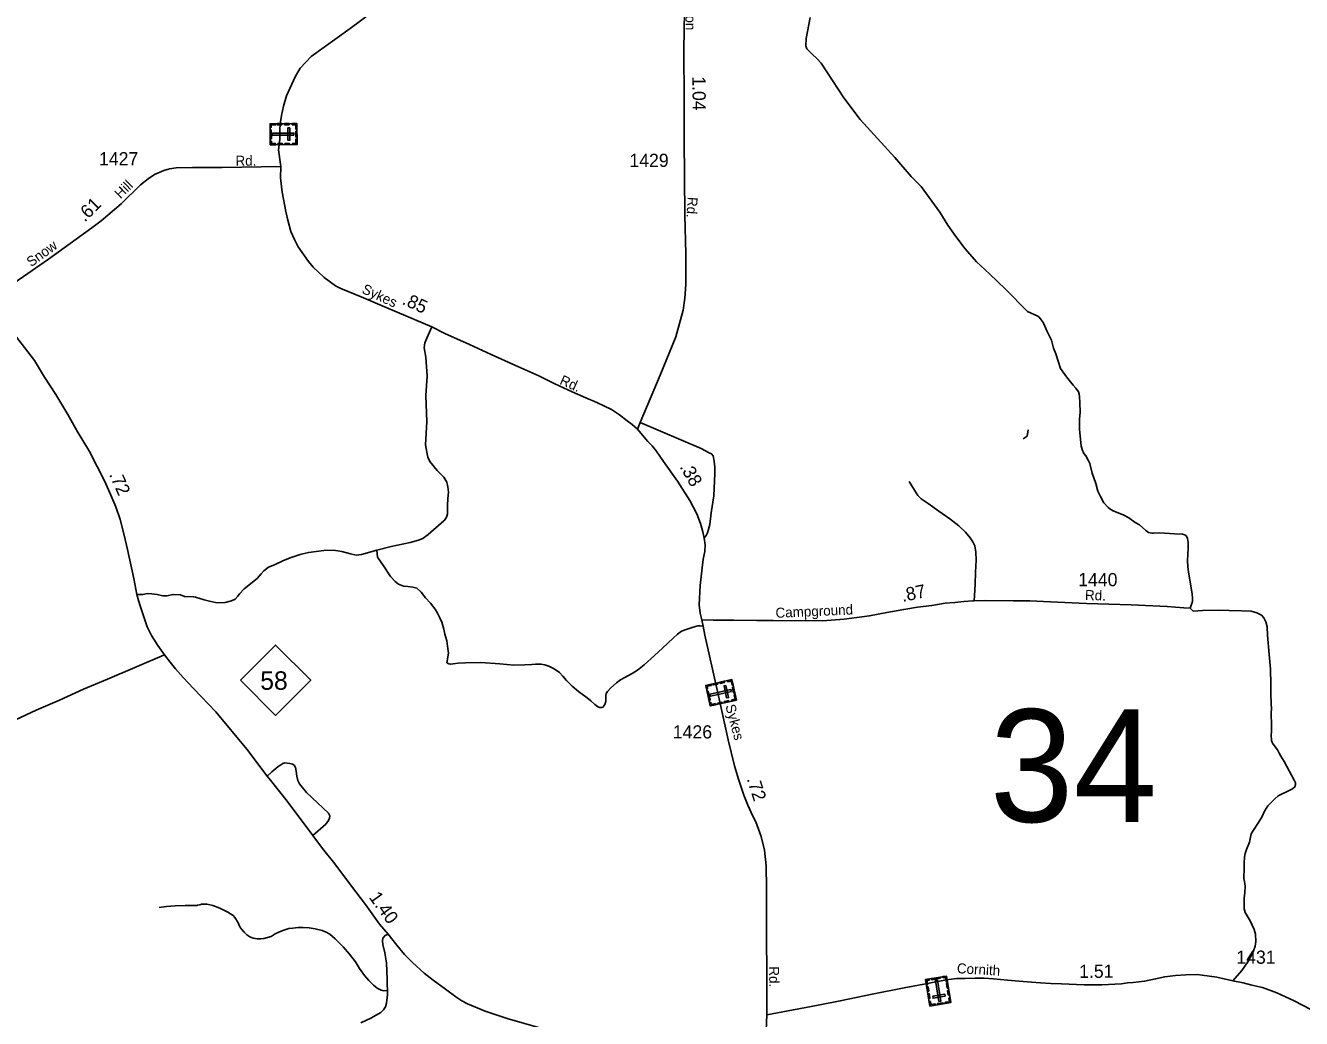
# Model space of a CAD drawing. Extents: x 2220236 to 2384410, y 720751 to 894131.
# Drawn here: x 2286305 to 2298391, y 822579 to 831981 of the extents above; entities that cross this region are included whole.
import ezdxf

# ---------------------------------------------------------------- set-up
doc = ezdxf.new("R2010")
doc.units = 0
doc.layers.add('Default', color=7, linetype='Continuous')

msp = doc.modelspace()

# ---------------------------------------------------------------- linework, layer by layer
at = {"layer": 'Default'}
msp.add_line((2297337, 826463), (2297277, 826468), dxfattribs=at)
for points in [[(2292100, 828159), (2292128, 828223), (2292315, 828671), (2292466, 829034), (2292510, 829194), (2292534, 829287), (2292550, 829398), (2292559, 829530), (2292559, 829818), (2292550, 830184), (2292545, 830909), (2292543, 831273), (2292539, 831754), (2292552, 832468), (2292542, 832714), (2292533, 833135), (2292528, 833487), (2292523, 833575)], [(2289808, 832274), (2289379, 831954), (2289012, 831689), (2288907, 831576), (2288858, 831495), (2288777, 831315), (2288748, 831218), (2288729, 831128), (2288716, 831050), (2288713, 830990), (2288713, 830902), (2288700, 830804), (2288722, 830646)], [(2297337, 826463), (2297358, 826527), (2297358, 826559), (2297355, 826597), (2297321, 826807), (2297314, 826855), (2297312, 826915), (2297319, 827029), (2297316, 827085), (2297311, 827125), (2297305, 827140), (2297297, 827150), (2297285, 827158), (2297265, 827164), (2297189, 827169), (2297047, 827176), (2296993, 827173), (2296973, 827175), (2296943, 827182), (2296915, 827198), (2296856, 827252), (2296816, 827275), (2296754, 827320), (2296707, 827346), (2296607, 827387), (2296575, 827406), (2296559, 827418), (2296518, 827462), (2296486, 827521), (2296463, 827573), (2296442, 827643), (2296409, 827743), (2296386, 827834), (2296370, 827864), (2296349, 827908), (2296329, 827930), (2296315, 827965), (2296304, 828001), (2296287, 828155), (2296288, 828253), (2296293, 828321), (2296292, 828409), (2296289, 828467), (2296285, 828491), (2296279, 828513), (2296255, 828547), (2296228, 828576), (2296165, 828654), (2296109, 828733), (2296065, 828872), (2296043, 828926), (2296022, 829002), (2295979, 829091), (2295950, 829155), (2295944, 829169), (2295924, 829195), (2295910, 829217), (2295893, 829229), (2295795, 829272), (2295587, 829486), (2295436, 829630), (2295313, 829744), (2295206, 829866), (2295118, 829983), (2295040, 830092), (2294966, 830213), (2294789, 830458), (2294695, 830553), (2294538, 830732), (2294211, 831090), (2294055, 831296), (2293841, 831626), (2293802, 831665), (2293753, 831712), (2293705, 831760), (2293695, 831790), (2293700, 831858), (2293736, 832057)], [(2288722, 830646), (2288167, 830637), (2287886, 830637), (2287733, 830634), (2287669, 830623), (2287615, 830609), (2287527, 830569), (2287465, 830530), (2287393, 830472), (2287212, 830293), (2287021, 830132), (2286932, 830066), (2286523, 829770), (2286285, 829604), (2286114, 829487), (2285938, 829362)], [(2288722, 830646), (2288721, 830538), (2288736, 830403), (2288770, 830221), (2288788, 830137), (2288819, 830030), (2288852, 829954), (2288887, 829886), (2288984, 829747), (2289028, 829692), (2289073, 829652), (2289133, 829595), (2289240, 829516), (2289290, 829490), (2289483, 829412), (2289660, 829336), (2290154, 829129), (2290276, 829066), (2290509, 828961), (2290716, 828866), (2290940, 828765), (2291167, 828663), (2291318, 828588), (2291482, 828514), (2291613, 828455), (2291717, 828411), (2291783, 828381), (2291856, 828346), (2291931, 828295), (2292003, 828239), (2292050, 828203), (2292100, 828159)], [(2287620, 826023), (2287559, 826112), (2287498, 826205), (2287457, 826288), (2287395, 826476), (2287374, 826536), (2287360, 826592), (2287330, 826745), (2287270, 827021), (2287240, 827155), (2287202, 827303), (2287160, 827424), (2287114, 827533), (2287056, 827662), (2286910, 827948), (2286794, 828139), (2286705, 828298), (2286591, 828487), (2286485, 828652), (2286389, 828810), (2286296, 828931), (2286187, 829070), (2285938, 829362)], [(2290154, 829129), (2290119, 829050), (2290087, 828978), (2290080, 828928), (2290096, 828842), (2290108, 828661), (2290098, 828479), (2290105, 828229), (2290094, 828010), (2290105, 827940), (2290117, 827894), (2290136, 827854), (2290205, 827768), (2290266, 827704), (2290294, 827656), (2290306, 827613), (2290311, 827563), (2290306, 827504), (2290303, 827437), (2290303, 827378), (2290303, 827357), (2290296, 827336), (2290287, 827313), (2290268, 827292), (2290120, 827163), (2290069, 827124), (2290027, 827108), (2289948, 827087), (2289768, 827047), (2289632, 827012)], [(2292100, 828159), (2292199, 828042), (2292239, 828000), (2292279, 827955), (2292348, 827854), (2292480, 827666), (2292597, 827485), (2292664, 827358), (2292698, 827267), (2292719, 827188), (2292733, 827128), (2292744, 827064), (2292740, 827000), (2292725, 826927), (2292695, 826679), (2292685, 826497), (2292696, 826416), (2292712, 826353)], [(2292128, 828223), (2292704, 827977), (2292781, 827936), (2292804, 827926), (2292818, 827906), (2292828, 827857), (2292834, 827799), (2292834, 827738), (2292824, 827527), (2292800, 827367), (2292786, 827255), (2292765, 827177), (2292751, 827151), (2292733, 827128)], [(2295755, 828069), (2295793, 828093), (2295802, 828154)], [(2294674, 827663), (2294726, 827582), (2294758, 827532), (2294789, 827500), (2294855, 827456), (2294957, 827382), (2295060, 827311), (2295146, 827243), (2295207, 827185), (2295254, 827130), (2295277, 827091), (2295296, 827054), (2295306, 826994), (2295309, 826920), (2295304, 826804), (2295301, 826692), (2295293, 826584), (2295291, 826532)], [(2289632, 827012), (2289486, 826971), (2289438, 826967), (2289384, 826978), (2289300, 827001), (2289222, 827013), (2289130, 827010), (2288984, 826990), (2288906, 826971), (2288822, 826945), (2288747, 826914), (2288663, 826875), (2288605, 826853), (2288562, 826818), (2288538, 826788), (2288498, 826744), (2288375, 826647), (2288332, 826600), (2288316, 826578), (2288290, 826550), (2288256, 826534), (2288197, 826519), (2288121, 826516), (2288059, 826528), (2287997, 826543), (2287916, 826568), (2287896, 826572), (2287812, 826575), (2287774, 826591), (2287702, 826594), (2287642, 826580), (2287606, 826582), (2287552, 826593), (2287502, 826601), (2287460, 826602), (2287416, 826594), (2287360, 826592)], [(2289632, 827012), (2289639, 826947), (2289695, 826865), (2289763, 826765), (2289805, 826718), (2289838, 826690), (2289885, 826671), (2289927, 826669), (2289975, 826662), (2290010, 826653), (2290052, 826616), (2290094, 826562), (2290141, 826511), (2290184, 826455), (2290207, 826418), (2290226, 826378), (2290249, 826331), (2290267, 826266), (2290277, 826219), (2290294, 826156), (2290303, 826103), (2290312, 826037), (2290295, 825947), (2290314, 825937), (2290330, 825933), (2290356, 825937), (2290403, 825942), (2290473, 825947), (2290618, 825949), (2290797, 825937), (2290930, 825925), (2291035, 825928), (2291101, 825932), (2291135, 825935), (2291159, 825935), (2291189, 825933), (2291224, 825928), (2291262, 825914), (2291299, 825897), (2291331, 825877), (2291364, 825855), (2291394, 825821), (2291429, 825779), (2291483, 825727), (2291544, 825676), (2291625, 825616), (2291661, 825588), (2291696, 825553), (2291723, 825532), (2291742, 825524), (2291752, 825522), (2291765, 825522), (2291775, 825527), (2291784, 825539), (2291791, 825552), (2291800, 825581), (2291801, 825609), (2291803, 825639), (2291805, 825657), (2291817, 825676), (2291850, 825711), (2291903, 825756), (2291940, 825786), (2291976, 825804), (2292052, 825844), (2292101, 825876), (2292164, 825926), (2292262, 826016), (2292339, 826084), (2292438, 826180), (2292480, 826219), (2292517, 826245), (2292563, 826263), (2292619, 826280), (2292651, 826289), (2292672, 826296), (2292696, 826296), (2292723, 826294)], [(2292712, 826353), (2292819, 826351), (2293014, 826350), (2293231, 826346), (2293388, 826346), (2293853, 826343), (2294058, 826360), (2294299, 826390), (2294462, 826422), (2294623, 826452), (2294754, 826473), (2294888, 826490), (2295017, 826510), (2295106, 826518), (2295194, 826527), (2295278, 826532), (2295291, 826532), (2295400, 826538), (2295661, 826533), (2295819, 826533), (2296014, 826523), (2296355, 826509), (2296776, 826495), (2297118, 826479), (2297277, 826468)], [(2297741, 822936), (2297825, 823034), (2297882, 823114), (2297916, 823177), (2297937, 823221), (2297953, 823265), (2297960, 823309), (2297956, 823377), (2297943, 823421), (2297904, 823502), (2297886, 823534), (2297857, 823582), (2297849, 823618), (2297847, 823656), (2297848, 823720), (2297853, 823768), (2297857, 823832), (2297850, 823876), (2297844, 823903), (2297849, 824004), (2297848, 824048), (2297852, 824105), (2297857, 824142), (2297871, 824180), (2297900, 824248), (2297915, 824328), (2297929, 824354), (2297984, 824435), (2298018, 824491), (2298041, 824541), (2298072, 824592), (2298138, 824660), (2298169, 824687), (2298281, 824740), (2298307, 824754), (2298327, 824772), (2298334, 824794), (2298334, 824810), (2298320, 824834), (2298228, 825012), (2298196, 825062), (2298181, 825090), (2298164, 825122), (2298140, 825152), (2298117, 825186), (2298107, 825211), (2298103, 825264), (2298107, 825291), (2298107, 825339), (2298105, 825484), (2298108, 825506), (2298104, 825566), (2298099, 825651), (2298102, 825745), (2298097, 825885), (2298086, 826024), (2298070, 826207), (2298065, 826288), (2298054, 826336), (2298033, 826372), (2298012, 826398), (2297969, 826420), (2297914, 826436), (2297827, 826439), (2297707, 826443), (2297608, 826444), (2297453, 826443), (2297365, 826437), (2297337, 826463)], [(2292712, 826353), (2292723, 826294), (2292740, 826207), (2292776, 826040), (2292819, 825858), (2292859, 825675), (2292896, 825503), (2292961, 825218), (2293019, 824972), (2293058, 824846), (2293108, 824692), (2293147, 824598), (2293193, 824495), (2293221, 824442), (2293272, 824303), (2293303, 824173), (2293321, 824025), (2293325, 823814), (2293322, 823595), (2293323, 823340), (2293326, 823015), (2293328, 822612)], [(2286210, 825407), (2286405, 825497), (2286626, 825593), (2286853, 825697), (2287080, 825793), (2287620, 826023)], [(2291187, 822487), (2290866, 822580), (2290660, 822648), (2290490, 822718), (2290437, 822746), (2290381, 822784), (2290283, 822855), (2290166, 822941), (2290082, 823009), (2289970, 823108), (2289896, 823185), (2289823, 823273), (2289741, 823378), (2289659, 823472), (2289525, 823657), (2289393, 823833), (2289235, 824042), (2289118, 824187), (2289025, 824312), (2288782, 824637), (2288626, 824837), (2288595, 824874), (2288401, 825130), (2288108, 825482), (2287897, 825705), (2287797, 825808), (2287727, 825889), (2287676, 825954), (2287620, 826023)], [(2288595, 824874), (2288638, 824915), (2288675, 824946), (2288699, 824966), (2288723, 824982), (2288742, 824992), (2288760, 824999), (2288809, 824993), (2288833, 824986), (2288849, 824976), (2288861, 824954), (2288867, 824920), (2288874, 824872), (2288884, 824832), (2288901, 824800), (2288965, 824719), (2289175, 824523), (2289187, 824497), (2289185, 824475), (2289176, 824455), (2289150, 824419), (2289025, 824312)], [(2287571, 823630), (2287640, 823639), (2287722, 823645), (2287817, 823648), (2287880, 823648), (2287906, 823648), (2287927, 823650), (2287935, 823652), (2287956, 823655), (2287973, 823660), (2287994, 823662), (2288024, 823660), (2288079, 823650), (2288145, 823625), (2288222, 823585), (2288272, 823553), (2288287, 823534), (2288316, 823492), (2288335, 823448), (2288354, 823421), (2288375, 823395), (2288400, 823372), (2288428, 823351), (2288460, 823339), (2288500, 823332), (2288533, 823332), (2288563, 823335), (2288597, 823346), (2288632, 823356), (2288670, 823379), (2288709, 823400), (2288753, 823416), (2288798, 823430), (2288837, 823435), (2288886, 823439), (2288934, 823441), (2288992, 823437), (2289048, 823427), (2289115, 823413), (2289153, 823397), (2289188, 823376), (2289237, 823334), (2289313, 823258), (2289374, 823189), (2289431, 823114), (2289467, 823051), (2289515, 822986), (2289558, 822937), (2289600, 822893), (2289635, 822865), (2289672, 822848), (2289700, 822842), (2289731, 822844)], [(2289480, 822539), (2289576, 822583), (2289669, 822635), (2289697, 822661), (2289715, 822688), (2289725, 822723), (2289732, 822802), (2289729, 822948), (2289725, 823106), (2289708, 823201), (2289688, 823278), (2289687, 823313), (2289690, 823338), (2289711, 823366), (2289741, 823378)], [(2298479, 822665), (2298322, 822747), (2298157, 822823), (2298021, 822872), (2297921, 822895), (2297840, 822915), (2297741, 822936), (2297590, 822970), (2297449, 822989), (2297403, 822994), (2297294, 822992), (2297196, 822985), (2297096, 822974), (2297009, 822953), (2296905, 822932), (2296797, 822920), (2296743, 822916), (2296685, 822907), (2296499, 822899), (2296331, 822897), (2296117, 822907), (2296016, 822910), (2295919, 822917), (2295834, 822922), (2295718, 822932), (2295607, 822942), (2295475, 822955), (2295385, 822960), (2295299, 822961), (2295205, 822958), (2295126, 822956), (2295025, 822945), (2294849, 822911), (2294628, 822869), (2294325, 822808), (2294022, 822745), (2293814, 822706), (2293579, 822662), (2293328, 822612)], [(2293328, 822612), (2293319, 822465), (2293323, 822241), (2293334, 821787)]]:
    msp.add_lwpolyline(points, dxfattribs=at)
for points in [[(2288875, 831053), (2288877, 830854), (2288623, 830852), (2288621, 831051)], [(2288621, 831018), (2288633, 831018), (2288632, 831040), (2288673, 831040), (2288673, 831051), (2288621, 831051)], [(2288691, 831052), (2288734, 831052), (2288734, 831041), (2288691, 831040)], [(2288758, 831052), (2288801, 831053), (2288801, 831041), (2288758, 831041)], [(2288832, 831053), (2288832, 831041), (2288864, 831042), (2288865, 831001), (2288876, 831001), (2288875, 831053)], [(2288633, 830994), (2288634, 830909), (2288622, 830909), (2288621, 830993)], [(2288847, 830944), (2288847, 830963), (2288644, 830961), (2288644, 830942)], [(2288808, 831012), (2288789, 831012), (2288790, 830894), (2288809, 830894)], [(2288876, 830979), (2288877, 830927), (2288865, 830927), (2288865, 830979)], [(2288622, 830885), (2288634, 830885), (2288634, 830863), (2288674, 830863), (2288675, 830852), (2288623, 830852)], [(2288695, 830864), (2288738, 830864), (2288738, 830853), (2288695, 830852)], [(2288761, 830864), (2288804, 830865), (2288804, 830853), (2288761, 830853)], [(2288834, 830854), (2288834, 830865), (2288866, 830865), (2288866, 830906), (2288877, 830906), (2288877, 830854)], [(2288341, 825781), (2288674, 826114), (2289007, 825781), (2288674, 825448)], [(2292996, 825788), (2293039, 825593), (2292791, 825538), (2292748, 825733)], [(2292755, 825701), (2292766, 825703), (2292761, 825725), (2292801, 825733), (2292799, 825744), (2292748, 825733)], [(2292816, 825748), (2292858, 825757), (2292861, 825746), (2292819, 825737)], [(2292882, 825762), (2292924, 825772), (2292927, 825761), (2292884, 825751)], [(2292939, 825733), (2292921, 825729), (2292946, 825614), (2292964, 825618)], [(2292954, 825778), (2292957, 825767), (2292988, 825774), (2292997, 825735), (2293008, 825737), (2292996, 825788)], [(2292771, 825679), (2292790, 825596), (2292779, 825594), (2292760, 825677)], [(2292991, 825675), (2292987, 825693), (2292789, 825649), (2292793, 825631)], [(2292997, 825584), (2292995, 825595), (2293026, 825602), (2293017, 825642), (2293028, 825644), (2293039, 825593)], [(2293012, 825715), (2293024, 825665), (2293012, 825662), (2293001, 825713)], [(2292784, 825571), (2292795, 825573), (2292800, 825552), (2292839, 825560), (2292841, 825550), (2292791, 825538)], [(2292859, 825565), (2292901, 825574), (2292904, 825563), (2292861, 825554)], [(2292923, 825579), (2292966, 825589), (2292968, 825577), (2292926, 825568)], [(2295069, 822729), (2294872, 822697), (2294831, 822948), (2295027, 822980)], [(2294864, 822953), (2294866, 822942), (2294844, 822939), (2294850, 822899), (2294839, 822897), (2294831, 822948)], [(2294973, 822960), (2294889, 822946), (2294887, 822957), (2294971, 822971)], [(2294956, 822740), (2294975, 822743), (2294942, 822943), (2294923, 822940)], [(2294995, 822975), (2294997, 822964), (2295018, 822967), (2295025, 822927), (2295036, 822929), (2295027, 822980)], [(2294854, 822879), (2294861, 822836), (2294850, 822834), (2294843, 822877)], [(2295039, 822911), (2295046, 822869), (2295035, 822867), (2295028, 822909)], [(2295050, 822845), (2295057, 822802), (2295045, 822800), (2295038, 822843)], [(2294865, 822814), (2294872, 822771), (2294860, 822769), (2294853, 822812)], [(2294865, 822740), (2294876, 822741), (2294881, 822710), (2294922, 822716), (2294923, 822705), (2294872, 822697)], [(2295017, 822790), (2295014, 822808), (2294898, 822789), (2294901, 822771)], [(2294996, 822717), (2294944, 822709), (2294943, 822720), (2294994, 822728)], [(2295062, 822772), (2295050, 822770), (2295056, 822738), (2295016, 822732), (2295017, 822721), (2295069, 822729)]]:
    msp.add_lwpolyline(points, close=True, dxfattribs=at)

# ---------------------------------------------------------------- texts
for s, height, rotation, p in [('Becton', 95, 270.2344, (2292556, 832331)), ('1.04', 125, 270.53, (2292621, 831500)), ('Rd.', 95, 0.5221, (2288294, 830653)), ('Hill', 95, 44.2908, (2287204, 830335)), ('.61', 125, 44.6487, (2286866, 830114)), ('Rd.', 95, 266.5506, (2292577, 830360)), ('Snow', 95, 35.8595, (2286358, 829691)), ('Sykes', 95, 335.4098, (2289483, 829452)), ('.85', 125, 335.4098, (2289864, 829346)), ('Rd.', 95, 336.1601, (2291357, 828588)), ('.38', 125, 299.8479, (2292498, 827803)), ('.72', 125, 293.9712, (2287094, 827731)), ('.87', 125, 11.8862, (2294613, 826522)), ('Rd.', 95, 358.1538, (2296339, 826542)), ('Campground', 95, 2.5402, (2293411, 826372)), ('Sykes', 95, 284.9294, (2292933, 825540)), ('.72', 125, 287.8285, (2293135, 824847)), ('1.40', 125, 305.9204, (2289553, 823725)), ('Rd.', 95, 270.823, (2293347, 823072)), ('Cornith', 95, 356.7614, (2295125, 823008)), ('1.51', 125, 0.18, (2296285, 822963))]:
    msp.add_text(s, height=height, rotation=rotation, dxfattribs=at).set_placement(p)
for s, height, p in [('1427', 125, (2287001, 830657)), ('1429', 125, (2292025, 830642)), ('1440', 125, (2296276, 826672)), ('58', 175, (2288528, 825691)), ('34', 1066.3, (2295438, 824440)), ('1426', 125, (2292436, 825230)), ('1431', 125, (2297774, 823097))]:
    msp.add_text(s, height=height, dxfattribs=at).set_placement(p)

doc.saveas('drawing.dxf')
